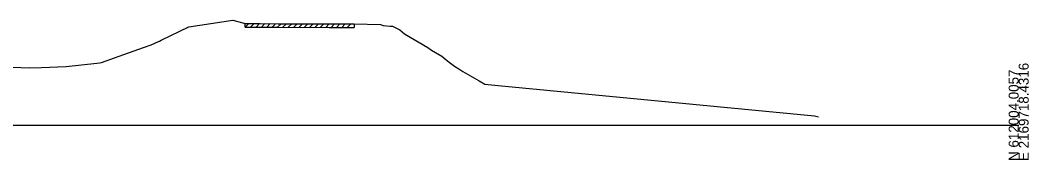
# Model space of a CAD drawing. Extents: x -26 to 6803, y -10 to 19606.
# Drawn here: x 2520.5 to 2802.8, y 3490.3 to 3529.4 of the extents above; entities that cross this region are included whole.
import ezdxf

# ---------------------------------------------------------------- set-up
doc = ezdxf.new("R2010")
doc.units = 0
for name, color, linetype in [('RD_GPK_XS_Cell', 7, 'Continuous'), ('RD_XS_ExGround', 7, 'Continuous'), ('RD_XS_ExPaveRet', 7, 'Continuous'), ('RD_XS_Milling', 7, 'Continuous')]:
    doc.layers.add(name, color=color, linetype=linetype)

msp = doc.modelspace()

# ---------------------------------------------------------------- linework, layer by layer
at = {"layer": 'RD_GPK_XS_Cell'}
msp.add_line((2400, 3500), (2800, 3500), dxfattribs=at)
at = {"layer": 'RD_XS_ExGround'}
msp.add_lwpolyline([(2508.83, 3516.51), (2520.64, 3516.2), (2523.23, 3516.08), (2526.43, 3516.21), (2533.38, 3516.47), (2541.9, 3517.43), (2542.66, 3517.5), (2543.28, 3517.59), (2546.89, 3518.89), (2554.98, 3521.77), (2557.11, 3522.51), (2559.17, 3523.47), (2559.49, 3523.6), (2559.91, 3523.81), (2567.67, 3527.54), (2580.04, 3529.44), (2583.5, 3528.46), (2587.62, 3528.46), (2592.71, 3528.45), (2606.95, 3528.39), (2614.01, 3528.37), (2621.35, 3528.19), (2622.07, 3527.95), (2624.02, 3527.8), (2624.67, 3527.76), (2626.78, 3526.73), (2628.1, 3525.61), (2634.56, 3521.74), (2635.66, 3521.03), (2638.55, 3519.33), (2639.61, 3518.42), (2640.54, 3517.7), (2642.06, 3516.59), (2643.28, 3515.81), (2644.44, 3515.1), (2649.01, 3512.42), (2650.6, 3511.47), (2654.32, 3511.13), (2742.84, 3502.62), (2743.97, 3502.39)], dxfattribs=at)
at = {"layer": 'RD_XS_ExPaveRet'}
for p, q in [((2583.5, 3527.46), (2584.5, 3528.46)), ((2583.5, 3527.46), (2583.5, 3528.46)), ((2583.5, 3527.46), (2587.62, 3527.46)), ((2583.5, 3527.46), (2583.5, 3527.46)), ((2585, 3527.46), (2586, 3528.46)), ((2586.5, 3527.46), (2587.5, 3528.46)), ((2587.62, 3527.46), (2592.71, 3527.45)), ((2588, 3527.46), (2589, 3528.46)), ((2589.5, 3527.46), (2590.5, 3528.46)), ((2591, 3527.46), (2592, 3528.45)), ((2592.5, 3527.45), (2593.5, 3528.45)), ((2592.71, 3527.45), (2606.95, 3527.39)), ((2594, 3527.45), (2595, 3528.44)), ((2595.5, 3527.44), (2596.5, 3528.43)), ((2597, 3527.43), (2598, 3528.43)), ((2598.5, 3527.43), (2599.5, 3528.42)), ((2600, 3527.42), (2601, 3528.41)), ((2601.5, 3527.41), (2602.5, 3528.41)), ((2603, 3527.4), (2604, 3528.4)), ((2604.5, 3527.4), (2605.5, 3528.39)), ((2606, 3527.39), (2607, 3528.39)), ((2606.95, 3527.39), (2614.01, 3527.37)), ((2607.5, 3527.39), (2608.5, 3528.38)), ((2609, 3527.38), (2610, 3528.38)), ((2610.5, 3527.38), (2611.5, 3528.38)), ((2612, 3527.37), (2613, 3528.37)), ((2614.01, 3528.37), (2614.01, 3527.37)), ((2614.01, 3527.37), (2614.01, 3527.37))]:
    msp.add_line(p, q, dxfattribs=at)
at = {"layer": 'RD_XS_Milling'}
msp.add_line((2583.5, 3526.46), (2583.5, 3526.46), dxfattribs=at)
msp.add_line((2583.5, 3526.46), (2583.5, 3526.46), dxfattribs=at)

# ---------------------------------------------------------------- texts
at = {"layer": 'RD_GPK_XS_Cell'}
for s, p in [('N 612004.0057', (2800, 3490)), ('E 2169718.4316', (2802.8, 3490))]:
    msp.add_text(s, height=2.8, rotation=90, dxfattribs=at).set_placement(p)

doc.saveas('drawing.dxf')
